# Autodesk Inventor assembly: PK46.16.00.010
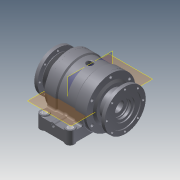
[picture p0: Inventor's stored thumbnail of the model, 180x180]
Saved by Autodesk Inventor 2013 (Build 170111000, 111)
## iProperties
Shininess: 64.0
Length Units: 11269
Angle Units: 11279
Time Units: 11290
Mass Units: 11283
Length Display Precision: 3
Angle Display Precision: 2
Compacted: True
Created: 2004-12
Part Number: PK46.16.00.010
Document SubType Name: Assembly
Designer: Salex
Manufacturer: Standard
Standards Organization: Custom
Mass: 20401.2 g
Surface Area: 8884.82 cm^2
Volume: 5540.42 cm^3
Density: 3.68224 g/cm^3
Density: 0.0
Volumn: 0.0
Area: 0.0
PropertySet Name: Model Information
Control State: 0
Master: False
Checked Out: False
Checked Out Date: 2008-10-09
Last Check In Date: 2008-10-09
Author: Salex
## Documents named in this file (7)
- D:\FrontLoaderVault\Data\Assy, Chassis, Front\PK46.16.10.000.iam
- D:\FrontLoaderVault\Data\Assy, Chassis, Front\TO-40.16.00.011.ipt
- D:\FrontLoaderVault\Data\Assy, Chassis, Front\TO-40.10.05.011.ipt
- D:\FrontLoaderVault\Data\Assy, Chassis, Front\PK46.16.00.010.ipt
- D:\FrontLoaderVault\Data\Assy, Chassis, Front\TO-40.20.00.011.ipt
- D:\FrontLoaderVault\Data\Assy, Chassis, Front\TO-40.25.00.011.ipt
- D:\FrontLoaderVault\Data\Assy, Chassis, Front\M10-6gx25.58.019.ipt
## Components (20 placed, 6 different names)
1. TO-40.16.00.011:1 — Insert:1, Mate:1, Insert:2, Insert:3, Mate:2, Angle:2, Insert:4, Insert:6, Insert:7
2. TO-40.10.05.011:1 — Insert:2, Angle:1
3. TO-40.10.05.011:2 — Insert:1, Mate:1, Angle:1
4. PK46.16.00.010:1 — Insert:3, Flush:1
5. PK46.16.00.010:2 — Insert:4
6. TO-40.20.00.011:1 — Flush:2, Insert:3, Insert:5
7. TO-40.25.00.011:1 — Insert:3
8. TO-40.25.00.011:2 — Insert:5
9. M10-6gx25.58.019:2 — Insert:7
10. M10-6gx25.58.019:1 — Insert:6
11. M10-6gx25.58.019:3
12. M10-6gx25.58.019:4
13. M10-6gx25.58.019:5
14. M10-6gx25.58.019:6
15. M10-6gx25.58.019:7
16. M10-6gx25.58.019:8
17. M10-6gx25.58.019:9
18. M10-6gx25.58.019:10
19. M10-6gx25.58.019:11
20. M10-6gx25.58.019:12
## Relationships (14: Insert 8, Mate 2, Angle 2, Flush 2)
- Insert:1: TO-40.16.00.011:1 ↔ TO-40.10.05.011:2
- Mate:1: TO-40.16.00.011:1 ↔ TO-40.10.05.011:2
- Insert:2: TO-40.16.00.011:1 ↔ TO-40.10.05.011:1
- Insert:3: TO-40.16.00.011:1 ↔ PK46.16.00.010:1
- Angle:1: TO-40.10.05.011:1 ↔ TO-40.10.05.011:2
- Mate:2: TO-40.16.00.011:1
- Angle:2: TO-40.16.00.011:1
- Insert:4: TO-40.16.00.011:1 ↔ PK46.16.00.010:2
- Flush:1: PK46.16.00.010:1
- Flush:2: TO-40.20.00.011:1
- Insert:3: TO-40.20.00.011:1 ↔ TO-40.25.00.011:1
- Insert:5: TO-40.20.00.011:1 ↔ TO-40.25.00.011:2
- Insert:6: TO-40.16.00.011:1 ↔ M10-6gx25.58.019:1
- Insert:7: TO-40.16.00.011:1 ↔ M10-6gx25.58.019:2
